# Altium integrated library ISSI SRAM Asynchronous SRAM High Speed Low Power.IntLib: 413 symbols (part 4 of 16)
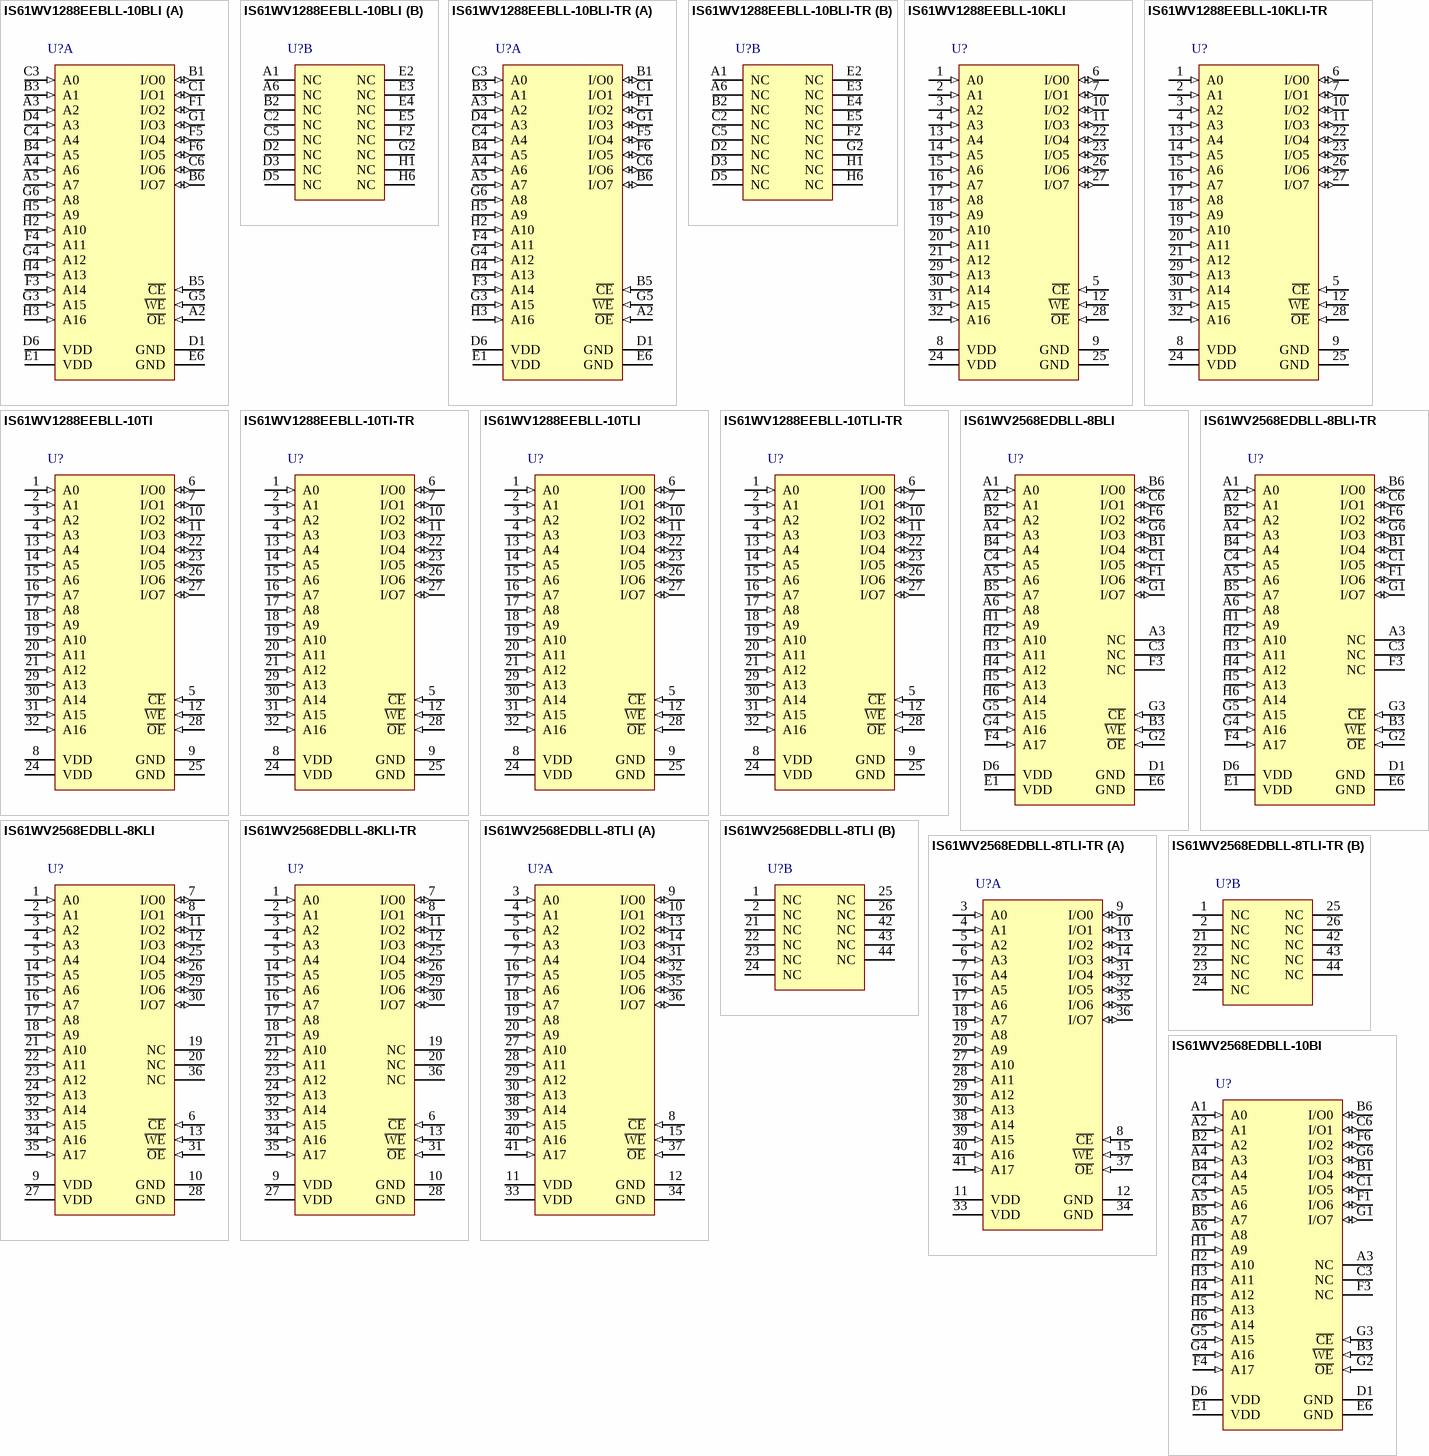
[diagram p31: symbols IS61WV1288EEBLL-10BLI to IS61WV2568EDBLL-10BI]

## IS61WV2568EDBLL-10BI
designator U?
2 M High Speed Asynchronous CMOS SRAM with ECC, 256 K x 8, -40 to 85 degC, 36-Pin BGA (TF-BGA-36); Manufacturer: Integrated Silicon Solution Inc (ISSI); PartNumber: IS61WV2568EDBLL-10BI; Density: 2M; Organization: 256K x 8; Packing: Tray / Tube; Speed (ns): 10
footprint ISSI-TF-BGA-36-6000x8000DE (BGA, 36-Balls, Body 8x6mm, Pitch 0.75mm)
pins: A1 A0 (in) "Address Input", A2 A1 (in) "Address Input", A3 NC "No Connection", A4 A3 (in) "Address Input", A5 A6 (in) "Address Input", A6 A8 (in) "Address Input", B1 I/O4 (io) "Bidirectional Port", B2 A2 (in) "Address Input", B3 ~{WE} (in) "Write Enable Input", B4 A4 (in) "Address Input", B5 A7 (in) "Address Input", B6 I/O0 (io) "Bidirectional Port", C1 I/O5 (io) "Bidirectional Port", C3 NC "No Connection", C4 A5 (in) "Address Input", C6 I/O1 (io) "Bidirectional Port", D1 GND (power) "Ground", D6 VDD (power) "Power", E1 VDD (power) "Power", E6 GND (power) "Ground", F1 I/O6 (io) "Bidirectional Port", F3 NC "No Connection", F4 A17 (in) "Address Input", F6 I/O2 (io) "Bidirectional Port", G1 I/O7 (io) "Bidirectional Port", G2 ~{OE} (in) "Output Enable Input", G3 ~{CE} (in) "Chip Enable Input", G4 A16 (in) "Address Input", G5 A15 (in) "Address Input", G6 I/O3 (io) "Bidirectional Port", H1 A9 (in) "Address Input", H2 A10 (in) "Address Input", H3 A11 (in) "Address Input", H4 A12 (in) "Address Input", H5 A13 (in) "Address Input", H6 A14 (in) "Address Input"

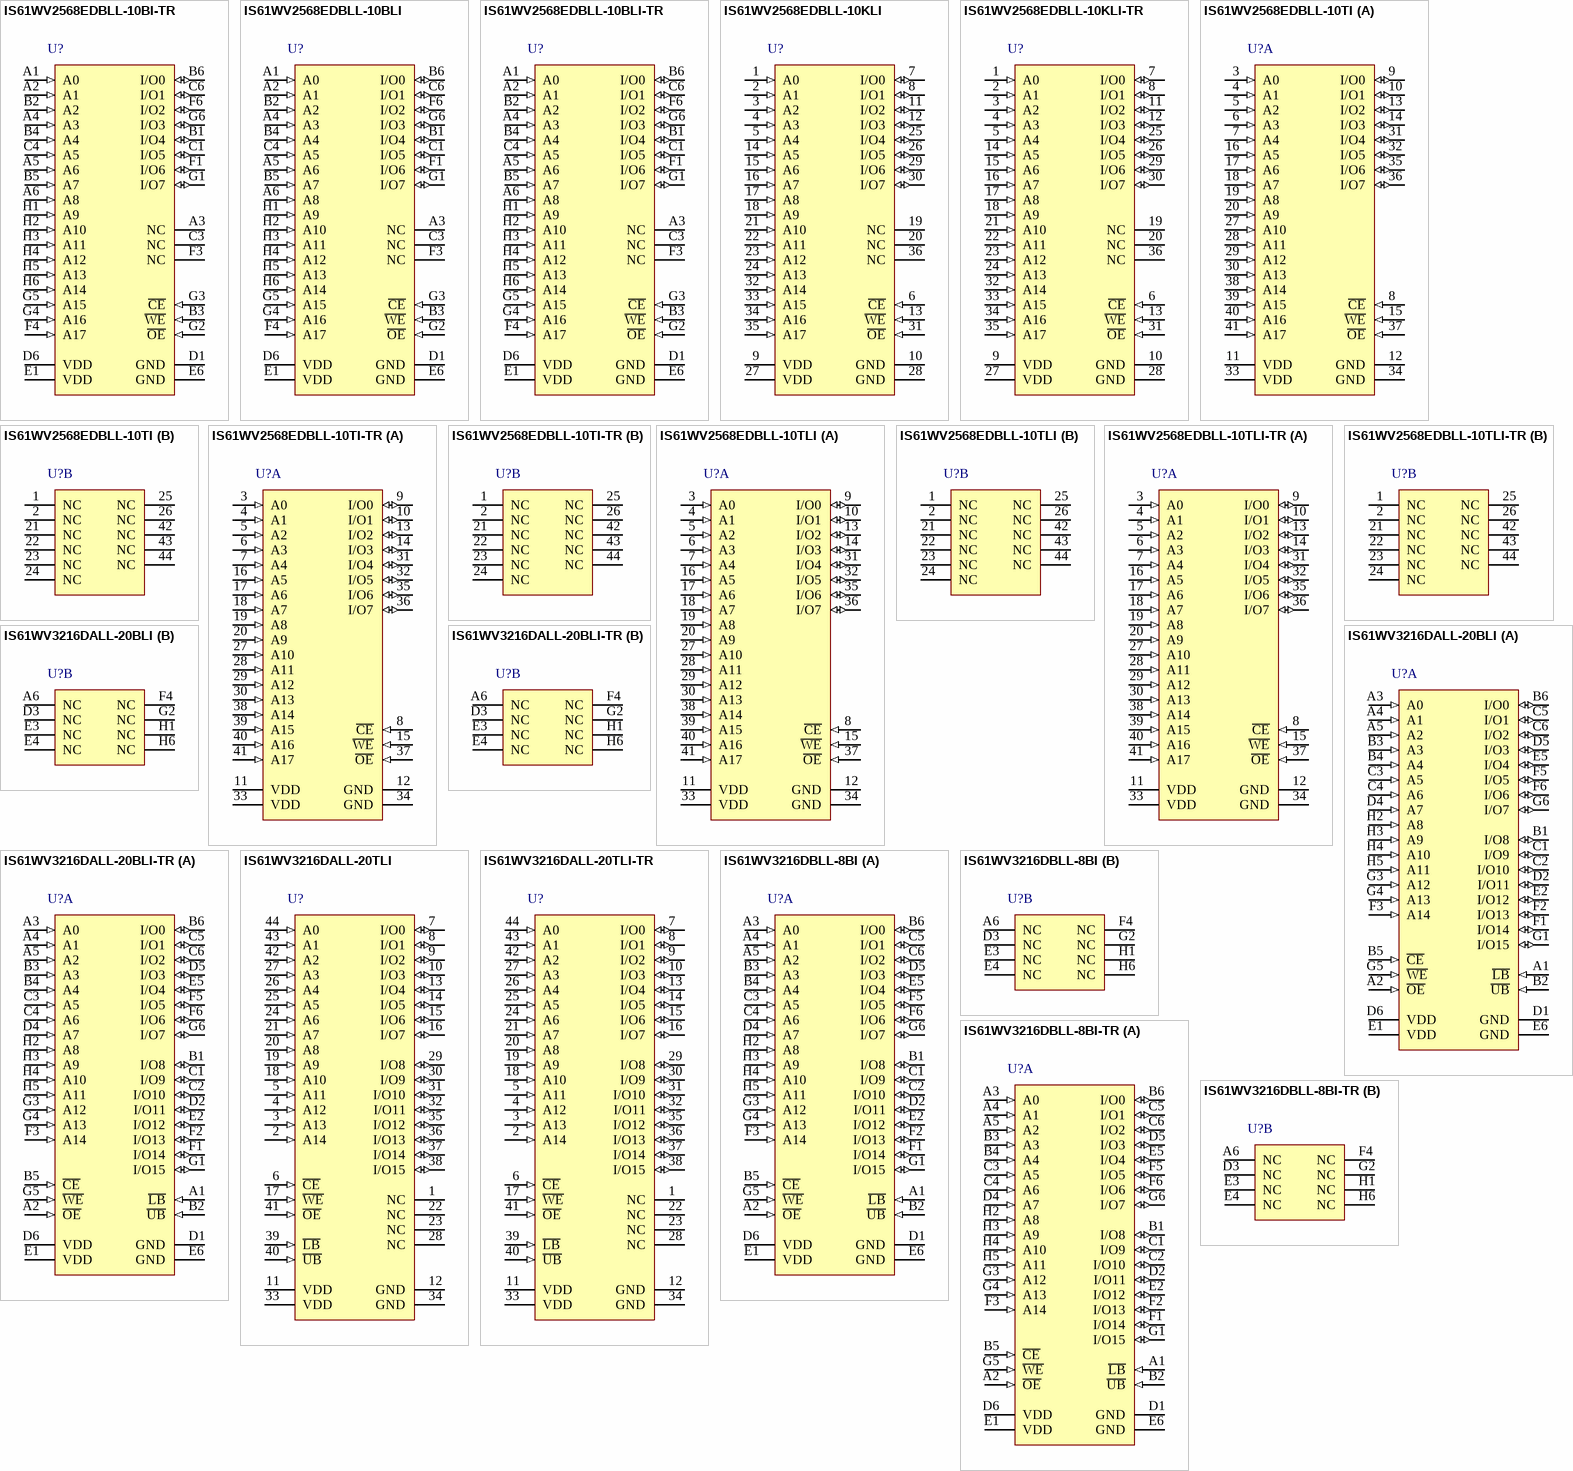
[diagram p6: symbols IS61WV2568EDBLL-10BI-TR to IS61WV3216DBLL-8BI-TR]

## IS61WV2568EDBLL-10BI-TR
designator U?
2 M High Speed Asynchronous CMOS SRAM with ECC, 256 K x 8, -40 to 85 degC, 36-Pin BGA (TF-BGA-36); Manufacturer: Integrated Silicon Solution Inc (ISSI); PartNumber: IS61WV2568EDBLL-10BI-TR; Density: 2M; Organization: 256K x 8; Packing: Tape & Reel; Speed (ns): 10
footprint ISSI-TF-BGA-36-6000x8000DE (BGA, 36-Balls, Body 8x6mm, Pitch 0.75mm)
pins: A1 A0 (in) "Address Input", A2 A1 (in) "Address Input", A3 NC "No Connection", A4 A3 (in) "Address Input", A5 A6 (in) "Address Input", A6 A8 (in) "Address Input", B1 I/O4 (io) "Bidirectional Port", B2 A2 (in) "Address Input", B3 ~{WE} (in) "Write Enable Input", B4 A4 (in) "Address Input", B5 A7 (in) "Address Input", B6 I/O0 (io) "Bidirectional Port", C1 I/O5 (io) "Bidirectional Port", C3 NC "No Connection", C4 A5 (in) "Address Input", C6 I/O1 (io) "Bidirectional Port", D1 GND (power) "Ground", D6 VDD (power) "Power", E1 VDD (power) "Power", E6 GND (power) "Ground", F1 I/O6 (io) "Bidirectional Port", F3 NC "No Connection", F4 A17 (in) "Address Input", F6 I/O2 (io) "Bidirectional Port", G1 I/O7 (io) "Bidirectional Port", G2 ~{OE} (in) "Output Enable Input", G3 ~{CE} (in) "Chip Enable Input", G4 A16 (in) "Address Input", G5 A15 (in) "Address Input", G6 I/O3 (io) "Bidirectional Port", H1 A9 (in) "Address Input", H2 A10 (in) "Address Input", H3 A11 (in) "Address Input", H4 A12 (in) "Address Input", H5 A13 (in) "Address Input", H6 A14 (in) "Address Input"

## IS61WV2568EDBLL-10BLI
designator U?
2 M High Speed Asynchronous CMOS SRAM with ECC, 256 K x 8, -40 to 85 degC, 36-Pin BGA (TF-BGA-36), Pb-Free; Manufacturer: Integrated Silicon Solution Inc (ISSI); PartNumber: IS61WV2568EDBLL-10BLI; Density: 2M; Organization: 256K x 8; Packing: Tray / Tube; Speed (ns): 10
footprint ISSI-TF-BGA-36-6000x8000DE (BGA, 36-Balls, Body 8x6mm, Pitch 0.75mm)
pins: A1 A0 (in) "Address Input", A2 A1 (in) "Address Input", A3 NC "No Connection", A4 A3 (in) "Address Input", A5 A6 (in) "Address Input", A6 A8 (in) "Address Input", B1 I/O4 (io) "Bidirectional Port", B2 A2 (in) "Address Input", B3 ~{WE} (in) "Write Enable Input", B4 A4 (in) "Address Input", B5 A7 (in) "Address Input", B6 I/O0 (io) "Bidirectional Port", C1 I/O5 (io) "Bidirectional Port", C3 NC "No Connection", C4 A5 (in) "Address Input", C6 I/O1 (io) "Bidirectional Port", D1 GND (power) "Ground", D6 VDD (power) "Power", E1 VDD (power) "Power", E6 GND (power) "Ground", F1 I/O6 (io) "Bidirectional Port", F3 NC "No Connection", F4 A17 (in) "Address Input", F6 I/O2 (io) "Bidirectional Port", G1 I/O7 (io) "Bidirectional Port", G2 ~{OE} (in) "Output Enable Input", G3 ~{CE} (in) "Chip Enable Input", G4 A16 (in) "Address Input", G5 A15 (in) "Address Input", G6 I/O3 (io) "Bidirectional Port", H1 A9 (in) "Address Input", H2 A10 (in) "Address Input", H3 A11 (in) "Address Input", H4 A12 (in) "Address Input", H5 A13 (in) "Address Input", H6 A14 (in) "Address Input"

## IS61WV2568EDBLL-10BLI-TR
designator U?
2 M High Speed Asynchronous CMOS SRAM with ECC, 256 K x 8, -40 to 85 degC, 36-Pin BGA (TF-BGA-36), Pb-Free; Manufacturer: Integrated Silicon Solution Inc (ISSI); PartNumber: IS61WV2568EDBLL-10BLI-TR; Density: 2M; Organization: 256K x 8; Packing: Tape & Reel; Speed (ns): 10
footprint ISSI-TF-BGA-36-6000x8000DE (BGA, 36-Balls, Body 8x6mm, Pitch 0.75mm)
pins: A1 A0 (in) "Address Input", A2 A1 (in) "Address Input", A3 NC "No Connection", A4 A3 (in) "Address Input", A5 A6 (in) "Address Input", A6 A8 (in) "Address Input", B1 I/O4 (io) "Bidirectional Port", B2 A2 (in) "Address Input", B3 ~{WE} (in) "Write Enable Input", B4 A4 (in) "Address Input", B5 A7 (in) "Address Input", B6 I/O0 (io) "Bidirectional Port", C1 I/O5 (io) "Bidirectional Port", C3 NC "No Connection", C4 A5 (in) "Address Input", C6 I/O1 (io) "Bidirectional Port", D1 GND (power) "Ground", D6 VDD (power) "Power", E1 VDD (power) "Power", E6 GND (power) "Ground", F1 I/O6 (io) "Bidirectional Port", F3 NC "No Connection", F4 A17 (in) "Address Input", F6 I/O2 (io) "Bidirectional Port", G1 I/O7 (io) "Bidirectional Port", G2 ~{OE} (in) "Output Enable Input", G3 ~{CE} (in) "Chip Enable Input", G4 A16 (in) "Address Input", G5 A15 (in) "Address Input", G6 I/O3 (io) "Bidirectional Port", H1 A9 (in) "Address Input", H2 A10 (in) "Address Input", H3 A11 (in) "Address Input", H4 A12 (in) "Address Input", H5 A13 (in) "Address Input", H6 A14 (in) "Address Input"

## IS61WV2568EDBLL-10KLI
designator U?
2 M High Speed Asynchronous CMOS SRAM with ECC, 256 K x 8, -40 to 85 degC, 36-Pin SOJ (SOJ-36), Pb-Free; Manufacturer: Integrated Silicon Solution Inc (ISSI); PartNumber: IS61WV2568EDBLL-10KLI; Density: 2M; Organization: 256K x 8; Packing: Tray / Tube; Speed (ns): 10
footprint ISSI-SOJ-36_N (SOJ, 36-Leads, Body 23.62x10.29mm, Pitch 1.27mm, IPC Medium Density)
pins: 1 A0 (in) "Address Input", 2 A1 (in) "Address Input", 3 A2 (in) "Address Input", 4 A3 (in) "Address Input", 5 A4 (in) "Address Input", 6 ~{CE} (in) "Chip Enable Input", 7 I/O0 (io) "Bidirectional Port", 8 I/O1 (io) "Bidirectional Port", 9 VDD (power) "Power", 10 GND (power) "Ground", 11 I/O2 (io) "Bidirectional Port", 12 I/O3 (io) "Bidirectional Port", 13 ~{WE} (in) "Write Enable Input", 14 A5 (in) "Address Input", 15 A6 (in) "Address Input", 16 A7 (in) "Address Input", 17 A8 (in) "Address Input", 18 A9 (in) "Address Input", 19 NC "No Connection", 20 NC "No Connection", 21 A10 (in) "Address Input", 22 A11 (in) "Address Input", 23 A12 (in) "Address Input", 24 A13 (in) "Address Input", 25 I/O4 (io) "Bidirectional Port", 26 I/O5 (io) "Bidirectional Port", 27 VDD (power) "Power", 28 GND (power) "Ground", 29 I/O6 (io) "Bidirectional Port", 30 I/O7 (io) "Bidirectional Port", 31 ~{OE} (in) "Output Enable Input", 32 A14 (in) "Address Input", 33 A15 (in) "Address Input", 34 A16 (in) "Address Input", 35 A17 (in) "Address Input", 36 NC "No Connection"

## IS61WV2568EDBLL-10KLI-TR
designator U?
2 M High Speed Asynchronous CMOS SRAM with ECC, 256 K x 8, -40 to 85 degC, 36-Pin SOJ (SOJ-36), Pb-Free; Manufacturer: Integrated Silicon Solution Inc (ISSI); PartNumber: IS61WV2568EDBLL-10KLI-TR; Density: 2M; Organization: 256K x 8; Packing: Tape & Reel; Speed (ns): 10
footprint ISSI-SOJ-36_N (SOJ, 36-Leads, Body 23.62x10.29mm, Pitch 1.27mm, IPC Medium Density)
pins: 1 A0 (in) "Address Input", 2 A1 (in) "Address Input", 3 A2 (in) "Address Input", 4 A3 (in) "Address Input", 5 A4 (in) "Address Input", 6 ~{CE} (in) "Chip Enable Input", 7 I/O0 (io) "Bidirectional Port", 8 I/O1 (io) "Bidirectional Port", 9 VDD (power) "Power", 10 GND (power) "Ground", 11 I/O2 (io) "Bidirectional Port", 12 I/O3 (io) "Bidirectional Port", 13 ~{WE} (in) "Write Enable Input", 14 A5 (in) "Address Input", 15 A6 (in) "Address Input", 16 A7 (in) "Address Input", 17 A8 (in) "Address Input", 18 A9 (in) "Address Input", 19 NC "No Connection", 20 NC "No Connection", 21 A10 (in) "Address Input", 22 A11 (in) "Address Input", 23 A12 (in) "Address Input", 24 A13 (in) "Address Input", 25 I/O4 (io) "Bidirectional Port", 26 I/O5 (io) "Bidirectional Port", 27 VDD (power) "Power", 28 GND (power) "Ground", 29 I/O6 (io) "Bidirectional Port", 30 I/O7 (io) "Bidirectional Port", 31 ~{OE} (in) "Output Enable Input", 32 A14 (in) "Address Input", 33 A15 (in) "Address Input", 34 A16 (in) "Address Input", 35 A17 (in) "Address Input", 36 NC "No Connection"

## IS61WV2568EDBLL-10TI
designator U?
2 M High Speed Asynchronous CMOS SRAM with ECC, 256 K x 8, -40 to 85 degC, 44-Pin SOP (TSOP-2-44); Manufacturer: Integrated Silicon Solution Inc (ISSI); PartNumber: IS61WV2568EDBLL-10TI; Density: 2M; Organization: 256K x 8; Packing: Tray / Tube; Speed (ns): 10
footprint ISSI-TSOP-2-44_N (SOP, 44-Leads, Body 18.5x10.3mm, Pitch 0.8mm, IPC Medium Density)
part A pins: 3 A0 (in) "Address Input", 4 A1 (in) "Address Input", 5 A2 (in) "Address Input", 6 A3 (in) "Address Input", 7 A4 (in) "Address Input", 8 ~{CE} (in) "Chip Enable Input", 9 I/O0 (io) "Bidirectional Port", 10 I/O1 (io) "Bidirectional Port", 11 VDD (power) "Power", 12 GND (power) "Ground", 13 I/O2 (io) "Bidirectional Port", 14 I/O3 (io) "Bidirectional Port", 15 ~{WE} (in) "Write Enable Input", 16 A5 (in) "Address Input", 17 A6 (in) "Address Input", 18 A7 (in) "Address Input", 19 A8 (in) "Address Input", 20 A9 (in) "Address Input", 27 A10 (in) "Address Input", 28 A11 (in) "Address Input", 29 A12 (in) "Address Input", 30 A13 (in) "Address Input", 31 I/O4 (io) "Bidirectional Port", 32 I/O5 (io) "Bidirectional Port", 33 VDD (power) "Power", 34 GND (power) "Ground", 35 I/O6 (io) "Bidirectional Port", 36 I/O7 (io) "Bidirectional Port", 37 ~{OE} (in) "Output Enable Input", 38 A14 (in) "Address Input", 39 A15 (in) "Address Input", 40 A16 (in) "Address Input", 41 A17 (in) "Address Input"
part B pins: 1 NC "No Connection", 2 NC "No Connection", 21 NC "No Connection", 22 NC "No Connection", 23 NC "No Connection", 24 NC "No Connection", 25 NC "No Connection", 26 NC "No Connection", 42 NC "No Connection", 43 NC "No Connection", 44 NC "No Connection"

## IS61WV2568EDBLL-10TI-TR
designator U?
2 M High Speed Asynchronous CMOS SRAM with ECC, 256 K x 8, -40 to 85 degC, 44-Pin SOP (TSOP-2-44); Manufacturer: Integrated Silicon Solution Inc (ISSI); PartNumber: IS61WV2568EDBLL-10TI-TR; Density: 2M; Organization: 256K x 8; Packing: Tape & Reel; Speed (ns): 10
footprint ISSI-TSOP-2-44_N (SOP, 44-Leads, Body 18.5x10.3mm, Pitch 0.8mm, IPC Medium Density)
part A pins: 3 A0 (in) "Address Input", 4 A1 (in) "Address Input", 5 A2 (in) "Address Input", 6 A3 (in) "Address Input", 7 A4 (in) "Address Input", 8 ~{CE} (in) "Chip Enable Input", 9 I/O0 (io) "Bidirectional Port", 10 I/O1 (io) "Bidirectional Port", 11 VDD (power) "Power", 12 GND (power) "Ground", 13 I/O2 (io) "Bidirectional Port", 14 I/O3 (io) "Bidirectional Port", 15 ~{WE} (in) "Write Enable Input", 16 A5 (in) "Address Input", 17 A6 (in) "Address Input", 18 A7 (in) "Address Input", 19 A8 (in) "Address Input", 20 A9 (in) "Address Input", 27 A10 (in) "Address Input", 28 A11 (in) "Address Input", 29 A12 (in) "Address Input", 30 A13 (in) "Address Input", 31 I/O4 (io) "Bidirectional Port", 32 I/O5 (io) "Bidirectional Port", 33 VDD (power) "Power", 34 GND (power) "Ground", 35 I/O6 (io) "Bidirectional Port", 36 I/O7 (io) "Bidirectional Port", 37 ~{OE} (in) "Output Enable Input", 38 A14 (in) "Address Input", 39 A15 (in) "Address Input", 40 A16 (in) "Address Input", 41 A17 (in) "Address Input"
part B pins: 1 NC "No Connection", 2 NC "No Connection", 21 NC "No Connection", 22 NC "No Connection", 23 NC "No Connection", 24 NC "No Connection", 25 NC "No Connection", 26 NC "No Connection", 42 NC "No Connection", 43 NC "No Connection", 44 NC "No Connection"

## IS61WV2568EDBLL-10TLI
designator U?
2 M High Speed Asynchronous CMOS SRAM with ECC, 256 K x 8, -40 to 85 degC, 44-Pin SOP (TSOP-2-44), Pb-Free; Manufacturer: Integrated Silicon Solution Inc (ISSI); PartNumber: IS61WV2568EDBLL-10TLI; Density: 2M; Organization: 256K x 8; Packing: Tray / Tube; Speed (ns): 10
footprint ISSI-TSOP-2-44_N (SOP, 44-Leads, Body 18.5x10.3mm, Pitch 0.8mm, IPC Medium Density)
part A pins: 3 A0 (in) "Address Input", 4 A1 (in) "Address Input", 5 A2 (in) "Address Input", 6 A3 (in) "Address Input", 7 A4 (in) "Address Input", 8 ~{CE} (in) "Chip Enable Input", 9 I/O0 (io) "Bidirectional Port", 10 I/O1 (io) "Bidirectional Port", 11 VDD (power) "Power", 12 GND (power) "Ground", 13 I/O2 (io) "Bidirectional Port", 14 I/O3 (io) "Bidirectional Port", 15 ~{WE} (in) "Write Enable Input", 16 A5 (in) "Address Input", 17 A6 (in) "Address Input", 18 A7 (in) "Address Input", 19 A8 (in) "Address Input", 20 A9 (in) "Address Input", 27 A10 (in) "Address Input", 28 A11 (in) "Address Input", 29 A12 (in) "Address Input", 30 A13 (in) "Address Input", 31 I/O4 (io) "Bidirectional Port", 32 I/O5 (io) "Bidirectional Port", 33 VDD (power) "Power", 34 GND (power) "Ground", 35 I/O6 (io) "Bidirectional Port", 36 I/O7 (io) "Bidirectional Port", 37 ~{OE} (in) "Output Enable Input", 38 A14 (in) "Address Input", 39 A15 (in) "Address Input", 40 A16 (in) "Address Input", 41 A17 (in) "Address Input"
part B pins: 1 NC "No Connection", 2 NC "No Connection", 21 NC "No Connection", 22 NC "No Connection", 23 NC "No Connection", 24 NC "No Connection", 25 NC "No Connection", 26 NC "No Connection", 42 NC "No Connection", 43 NC "No Connection", 44 NC "No Connection"

## IS61WV2568EDBLL-10TLI-TR
designator U?
2 M High Speed Asynchronous CMOS SRAM with ECC, 256 K x 8, -40 to 85 degC, 44-Pin SOP (TSOP-2-44), Pb-Free; Manufacturer: Integrated Silicon Solution Inc (ISSI); PartNumber: IS61WV2568EDBLL-10TLI-TR; Density: 2M; Organization: 256K x 8; Packing: Tape & Reel; Speed (ns): 10
footprint ISSI-TSOP-2-44_N (SOP, 44-Leads, Body 18.5x10.3mm, Pitch 0.8mm, IPC Medium Density)
part A pins: 3 A0 (in) "Address Input", 4 A1 (in) "Address Input", 5 A2 (in) "Address Input", 6 A3 (in) "Address Input", 7 A4 (in) "Address Input", 8 ~{CE} (in) "Chip Enable Input", 9 I/O0 (io) "Bidirectional Port", 10 I/O1 (io) "Bidirectional Port", 11 VDD (power) "Power", 12 GND (power) "Ground", 13 I/O2 (io) "Bidirectional Port", 14 I/O3 (io) "Bidirectional Port", 15 ~{WE} (in) "Write Enable Input", 16 A5 (in) "Address Input", 17 A6 (in) "Address Input", 18 A7 (in) "Address Input", 19 A8 (in) "Address Input", 20 A9 (in) "Address Input", 27 A10 (in) "Address Input", 28 A11 (in) "Address Input", 29 A12 (in) "Address Input", 30 A13 (in) "Address Input", 31 I/O4 (io) "Bidirectional Port", 32 I/O5 (io) "Bidirectional Port", 33 VDD (power) "Power", 34 GND (power) "Ground", 35 I/O6 (io) "Bidirectional Port", 36 I/O7 (io) "Bidirectional Port", 37 ~{OE} (in) "Output Enable Input", 38 A14 (in) "Address Input", 39 A15 (in) "Address Input", 40 A16 (in) "Address Input", 41 A17 (in) "Address Input"
part B pins: 1 NC "No Connection", 2 NC "No Connection", 21 NC "No Connection", 22 NC "No Connection", 23 NC "No Connection", 24 NC "No Connection", 25 NC "No Connection", 26 NC "No Connection", 42 NC "No Connection", 43 NC "No Connection", 44 NC "No Connection"

## IS61WV3216DALL-20BLI
designator U?
512 K High Speed Asynchronous CMOS SRAM, 32 K x 16, -40 to 85 degC, 48-Pin BGA (TF-BGA-48), Pb-Free; Manufacturer: Integrated Silicon Solution Inc (ISSI); PartNumber: IS61WV3216DALL-20BLI; Density: 512K; Organization: 32K x 16; Packing: Tray / Tube; Speed (ns): 20
footprint ISSI-TF-BGA-48-6000X8000DE (BGA, 48-Balls, Body 8x6mm, Pitch 0.75mm)
part A pins: A1 ~{LB} (in) "Lower-byte Control(I/O0-I/O7)", A2 ~{OE} (in) "Output Enable Input", A3 A0 (in) "Address Input", A4 A1 (in) "Address Input", A5 A2 (in) "Address Input", B1 I/O8 (io) "Data Input/Output", B2 ~{UB} (in) "Upper-byte Control(I/O8-I/O15)", B3 A3 (in) "Address Input", B4 A4 (in) "Address Input", B5 ~{CE} (in) "Chip Enable Input", B6 I/O0 (io) "Data Input/Output", C1 I/O9 (io) "Data Input/Output", C2 I/O10 (io) "Data Input/Output", C3 A5 (in) "Address Input", C4 A6 (in) "Address Input", C5 I/O1 (io) "Data Input/Output", C6 I/O2 (io) "Data Input/Output", D1 GND (power) "Ground", D2 I/O11 (io) "Data Input/Output", D4 A7 (in) "Address Input", D5 I/O3 (io) "Data Input/Output", D6 VDD (power) "Power", E1 VDD (power) "Power", E2 I/O12 (io) "Data Input/Output", E5 I/O4 (io) "Data Input/Output", E6 GND (power) "Ground", F1 I/O14 (io) "Data Input/Output", F2 I/O13 (io) "Data Input/Output", F3 A14 (in) "Address Input", F5 I/O5 (io) "Data Input/Output", F6 I/O6 (io) "Data Input/Output", G1 I/O15 (io) "Data Input/Output", G3 A12 (in) "Address Input", G4 A13 (in) "Address Input", G5 ~{WE} (in) "Write Enable Input", G6 I/O7 (io) "Data Input/Output", H2 A8 (in) "Address Input", H3 A9 (in) "Address Input", H4 A10 (in) "Address Input", H5 A11 (in) "Address Input"
part B pins: A6 NC "No Connection", D3 NC "No Connection", E3 NC "No Connection", E4 NC "No Connection", F4 NC "No Connection", G2 NC "No Connection", H1 NC "No Connection", H6 NC "No Connection"

## IS61WV3216DALL-20BLI-TR
designator U?
512 K High Speed Asynchronous CMOS SRAM, 32 K x 16, -40 to 85 degC, 48-Pin BGA (TF-BGA-48), Pb-Free; Manufacturer: Integrated Silicon Solution Inc (ISSI); PartNumber: IS61WV3216DALL-20BLI-TR; Density: 512K; Organization: 32K x 16; Packing: Tape & Reel; Speed (ns): 20
footprint ISSI-TF-BGA-48-6000X8000DE (BGA, 48-Balls, Body 8x6mm, Pitch 0.75mm)
part A pins: A1 ~{LB} (in) "Lower-byte Control(I/O0-I/O7)", A2 ~{OE} (in) "Output Enable Input", A3 A0 (in) "Address Input", A4 A1 (in) "Address Input", A5 A2 (in) "Address Input", B1 I/O8 (io) "Data Input/Output", B2 ~{UB} (in) "Upper-byte Control(I/O8-I/O15)", B3 A3 (in) "Address Input", B4 A4 (in) "Address Input", B5 ~{CE} (in) "Chip Enable Input", B6 I/O0 (io) "Data Input/Output", C1 I/O9 (io) "Data Input/Output", C2 I/O10 (io) "Data Input/Output", C3 A5 (in) "Address Input", C4 A6 (in) "Address Input", C5 I/O1 (io) "Data Input/Output", C6 I/O2 (io) "Data Input/Output", D1 GND (power) "Ground", D2 I/O11 (io) "Data Input/Output", D4 A7 (in) "Address Input", D5 I/O3 (io) "Data Input/Output", D6 VDD (power) "Power", E1 VDD (power) "Power", E2 I/O12 (io) "Data Input/Output", E5 I/O4 (io) "Data Input/Output", E6 GND (power) "Ground", F1 I/O14 (io) "Data Input/Output", F2 I/O13 (io) "Data Input/Output", F3 A14 (in) "Address Input", F5 I/O5 (io) "Data Input/Output", F6 I/O6 (io) "Data Input/Output", G1 I/O15 (io) "Data Input/Output", G3 A12 (in) "Address Input", G4 A13 (in) "Address Input", G5 ~{WE} (in) "Write Enable Input", G6 I/O7 (io) "Data Input/Output", H2 A8 (in) "Address Input", H3 A9 (in) "Address Input", H4 A10 (in) "Address Input", H5 A11 (in) "Address Input"
part B pins: A6 NC "No Connection", D3 NC "No Connection", E3 NC "No Connection", E4 NC "No Connection", F4 NC "No Connection", G2 NC "No Connection", H1 NC "No Connection", H6 NC "No Connection"

## IS61WV3216DALL-20TLI
designator U?
512 K High Speed Asynchronous CMOS SRAM, 32 K x 16, -40 to 85 degC, 44-Pin SOP (TSOP-2-44), Pb-Free; Manufacturer: Integrated Silicon Solution Inc (ISSI); PartNumber: IS61WV3216DALL-20TLI; Density: 512K; Organization: 32K x 16; Packing: Tray / Tube; Speed (ns): 20
footprint ISSI-TSOP-2-44_N (SOP, 44-Leads, Body 18.5x10.3mm, Pitch 0.8mm, IPC Medium Density)
pins: 1 NC "No Connection", 2 A14 (in) "Address Input", 3 A13 (in) "Address Input", 4 A12 (in) "Address Input", 5 A11 (in) "Address Input", 6 ~{CE} (in) "Chip Enable Input", 7 I/O0 (io) "Data Input/Output", 8 I/O1 (io) "Data Input/Output", 9 I/O2 (io) "Data Input/Output", 10 I/O3 (io) "Data Input/Output", 11 VDD (power) "Power", 12 GND (power) "Ground", 13 I/O4 (io) "Data Input/Output", 14 I/O5 (io) "Data Input/Output", 15 I/O6 (io) "Data Input/Output", 16 I/O7 (io) "Data Input/Output", 17 ~{WE} (in) "Write Enable Input", 18 A10 (in) "Address Input", 19 A9 (in) "Address Input", 20 A8 (in) "Address Input", 21 A7 (in) "Address Input", 22 NC "No Connection", 23 NC "No Connection", 24 A6 (in) "Address Input", 25 A5 (in) "Address Input", 26 A4 (in) "Address Input", 27 A3 (in) "Address Input", 28 NC "No Connection", 29 I/O8 (io) "Data Input/Output", 30 I/O9 (io) "Data Input/Output", 31 I/O10 (io) "Data Input/Output", 32 I/O11 (io) "Data Input/Output", 33 VDD (power) "Power", 34 GND (power) "Ground", 35 I/O12 (io) "Data Input/Output", 36 I/O13 (io) "Data Input/Output", 37 I/O14 (io) "Data Input/Output", 38 I/O15 (io) "Data Input/Output", 39 ~{LB} (in) "Lower-byte Control (I/O0-I/O7)", 40 ~{UB} (in) "Upper-byte Control (I/O8-I/O15)", 41 ~{OE} (in) "Output Enable Input", 42 A2 (in) "Address Input", 43 A1 (in) "Address Input", 44 A0 (in) "Address Input"

## IS61WV3216DALL-20TLI-TR
designator U?
512 K High Speed Asynchronous CMOS SRAM, 32 K x 16, -40 to 85 degC, 44-Pin SOP (TSOP-2-44), Pb-Free; Manufacturer: Integrated Silicon Solution Inc (ISSI); PartNumber: IS61WV3216DALL-20TLI-TR; Density: 512K; Organization: 32K x 16; Packing: Tape & Reel; Speed (ns): 20
footprint ISSI-TSOP-2-44_N (SOP, 44-Leads, Body 18.5x10.3mm, Pitch 0.8mm, IPC Medium Density)
pins: 1 NC "No Connection", 2 A14 (in) "Address Input", 3 A13 (in) "Address Input", 4 A12 (in) "Address Input", 5 A11 (in) "Address Input", 6 ~{CE} (in) "Chip Enable Input", 7 I/O0 (io) "Data Input/Output", 8 I/O1 (io) "Data Input/Output", 9 I/O2 (io) "Data Input/Output", 10 I/O3 (io) "Data Input/Output", 11 VDD (power) "Power", 12 GND (power) "Ground", 13 I/O4 (io) "Data Input/Output", 14 I/O5 (io) "Data Input/Output", 15 I/O6 (io) "Data Input/Output", 16 I/O7 (io) "Data Input/Output", 17 ~{WE} (in) "Write Enable Input", 18 A10 (in) "Address Input", 19 A9 (in) "Address Input", 20 A8 (in) "Address Input", 21 A7 (in) "Address Input", 22 NC "No Connection", 23 NC "No Connection", 24 A6 (in) "Address Input", 25 A5 (in) "Address Input", 26 A4 (in) "Address Input", 27 A3 (in) "Address Input", 28 NC "No Connection", 29 I/O8 (io) "Data Input/Output", 30 I/O9 (io) "Data Input/Output", 31 I/O10 (io) "Data Input/Output", 32 I/O11 (io) "Data Input/Output", 33 VDD (power) "Power", 34 GND (power) "Ground", 35 I/O12 (io) "Data Input/Output", 36 I/O13 (io) "Data Input/Output", 37 I/O14 (io) "Data Input/Output", 38 I/O15 (io) "Data Input/Output", 39 ~{LB} (in) "Lower-byte Control (I/O0-I/O7)", 40 ~{UB} (in) "Upper-byte Control (I/O8-I/O15)", 41 ~{OE} (in) "Output Enable Input", 42 A2 (in) "Address Input", 43 A1 (in) "Address Input", 44 A0 (in) "Address Input"

## IS61WV3216DBLL-8BI
designator U?
512 K High Speed Asynchronous CMOS SRAM, 32 K x 16, -40 to 85 degC, 48-Pin BGA (TF-BGA-48); Manufacturer: Integrated Silicon Solution Inc (ISSI); PartNumber: IS61WV3216DBLL-8BI; Density: 512K; Organization: 32K x 16; Packing: Tray / Tube; Speed (ns): 8
footprint ISSI-TF-BGA-48-6000X8000DE (BGA, 48-Balls, Body 8x6mm, Pitch 0.75mm)
part A pins: A1 ~{LB} (in) "Lower-byte Control(I/O0-I/O7)", A2 ~{OE} (in) "Output Enable Input", A3 A0 (in) "Address Input", A4 A1 (in) "Address Input", A5 A2 (in) "Address Input", B1 I/O8 (io) "Data Input/Output", B2 ~{UB} (in) "Upper-byte Control(I/O8-I/O15)", B3 A3 (in) "Address Input", B4 A4 (in) "Address Input", B5 ~{CE} (in) "Chip Enable Input", B6 I/O0 (io) "Data Input/Output", C1 I/O9 (io) "Data Input/Output", C2 I/O10 (io) "Data Input/Output", C3 A5 (in) "Address Input", C4 A6 (in) "Address Input", C5 I/O1 (io) "Data Input/Output", C6 I/O2 (io) "Data Input/Output", D1 GND (power) "Ground", D2 I/O11 (io) "Data Input/Output", D4 A7 (in) "Address Input", D5 I/O3 (io) "Data Input/Output", D6 VDD (power) "Power", E1 VDD (power) "Power", E2 I/O12 (io) "Data Input/Output", E5 I/O4 (io) "Data Input/Output", E6 GND (power) "Ground", F1 I/O14 (io) "Data Input/Output", F2 I/O13 (io) "Data Input/Output", F3 A14 (in) "Address Input", F5 I/O5 (io) "Data Input/Output", F6 I/O6 (io) "Data Input/Output", G1 I/O15 (io) "Data Input/Output", G3 A12 (in) "Address Input", G4 A13 (in) "Address Input", G5 ~{WE} (in) "Write Enable Input", G6 I/O7 (io) "Data Input/Output", H2 A8 (in) "Address Input", H3 A9 (in) "Address Input", H4 A10 (in) "Address Input", H5 A11 (in) "Address Input"
part B pins: A6 NC "No Connection", D3 NC "No Connection", E3 NC "No Connection", E4 NC "No Connection", F4 NC "No Connection", G2 NC "No Connection", H1 NC "No Connection", H6 NC "No Connection"

## IS61WV3216DBLL-8BI-TR
designator U?
512 K High Speed Asynchronous CMOS SRAM, 32 K x 16, -40 to 85 degC, 48-Pin BGA (TF-BGA-48); Manufacturer: Integrated Silicon Solution Inc (ISSI); PartNumber: IS61WV3216DBLL-8BI-TR; Density: 512K; Organization: 32K x 16; Packing: Tape & Reel; Speed (ns): 8
footprint ISSI-TF-BGA-48-6000X8000DE (BGA, 48-Balls, Body 8x6mm, Pitch 0.75mm)
part A pins: A1 ~{LB} (in) "Lower-byte Control(I/O0-I/O7)", A2 ~{OE} (in) "Output Enable Input", A3 A0 (in) "Address Input", A4 A1 (in) "Address Input", A5 A2 (in) "Address Input", B1 I/O8 (io) "Data Input/Output", B2 ~{UB} (in) "Upper-byte Control(I/O8-I/O15)", B3 A3 (in) "Address Input", B4 A4 (in) "Address Input", B5 ~{CE} (in) "Chip Enable Input", B6 I/O0 (io) "Data Input/Output", C1 I/O9 (io) "Data Input/Output", C2 I/O10 (io) "Data Input/Output", C3 A5 (in) "Address Input", C4 A6 (in) "Address Input", C5 I/O1 (io) "Data Input/Output", C6 I/O2 (io) "Data Input/Output", D1 GND (power) "Ground", D2 I/O11 (io) "Data Input/Output", D4 A7 (in) "Address Input", D5 I/O3 (io) "Data Input/Output", D6 VDD (power) "Power", E1 VDD (power) "Power", E2 I/O12 (io) "Data Input/Output", E5 I/O4 (io) "Data Input/Output", E6 GND (power) "Ground", F1 I/O14 (io) "Data Input/Output", F2 I/O13 (io) "Data Input/Output", F3 A14 (in) "Address Input", F5 I/O5 (io) "Data Input/Output", F6 I/O6 (io) "Data Input/Output", G1 I/O15 (io) "Data Input/Output", G3 A12 (in) "Address Input", G4 A13 (in) "Address Input", G5 ~{WE} (in) "Write Enable Input", G6 I/O7 (io) "Data Input/Output", H2 A8 (in) "Address Input", H3 A9 (in) "Address Input", H4 A10 (in) "Address Input", H5 A11 (in) "Address Input"
part B pins: A6 NC "No Connection", D3 NC "No Connection", E3 NC "No Connection", E4 NC "No Connection", F4 NC "No Connection", G2 NC "No Connection", H1 NC "No Connection", H6 NC "No Connection"

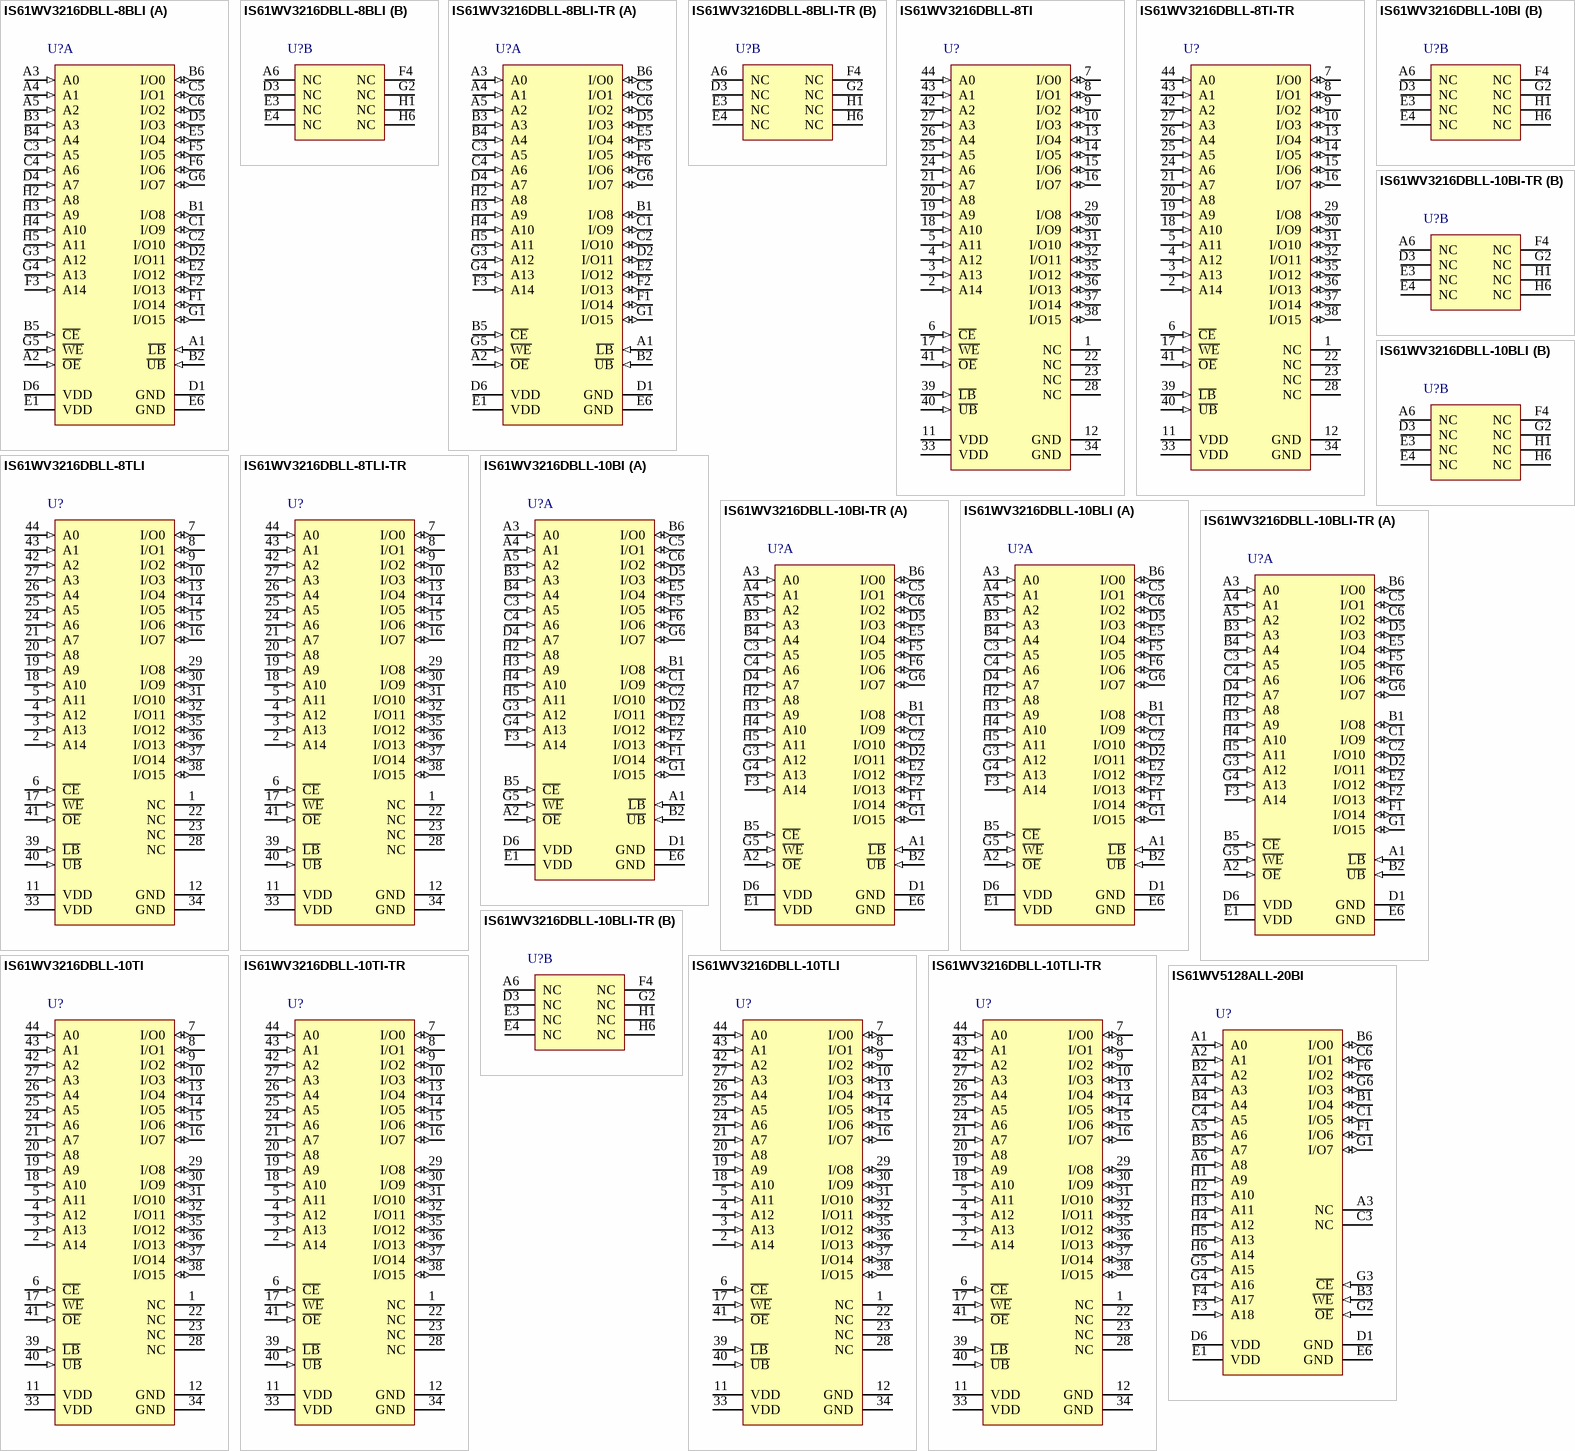
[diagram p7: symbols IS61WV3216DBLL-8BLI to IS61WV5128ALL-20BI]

## IS61WV3216DBLL-8BLI
designator U?
512 K High Speed Asynchronous CMOS SRAM, 32 K x 16, -40 to 85 degC, 48-Pin BGA (TF-BGA-48), Pb-Free; Manufacturer: Integrated Silicon Solution Inc (ISSI); PartNumber: IS61WV3216DBLL-8BLI; Density: 512K; Organization: 32K x 16; Packing: Tray / Tube; Speed (ns): 8
footprint ISSI-TF-BGA-48-6000X8000DE (BGA, 48-Balls, Body 8x6mm, Pitch 0.75mm)
part A pins: A1 ~{LB} (in) "Lower-byte Control(I/O0-I/O7)", A2 ~{OE} (in) "Output Enable Input", A3 A0 (in) "Address Input", A4 A1 (in) "Address Input", A5 A2 (in) "Address Input", B1 I/O8 (io) "Data Input/Output", B2 ~{UB} (in) "Upper-byte Control(I/O8-I/O15)", B3 A3 (in) "Address Input", B4 A4 (in) "Address Input", B5 ~{CE} (in) "Chip Enable Input", B6 I/O0 (io) "Data Input/Output", C1 I/O9 (io) "Data Input/Output", C2 I/O10 (io) "Data Input/Output", C3 A5 (in) "Address Input", C4 A6 (in) "Address Input", C5 I/O1 (io) "Data Input/Output", C6 I/O2 (io) "Data Input/Output", D1 GND (power) "Ground", D2 I/O11 (io) "Data Input/Output", D4 A7 (in) "Address Input", D5 I/O3 (io) "Data Input/Output", D6 VDD (power) "Power", E1 VDD (power) "Power", E2 I/O12 (io) "Data Input/Output", E5 I/O4 (io) "Data Input/Output", E6 GND (power) "Ground", F1 I/O14 (io) "Data Input/Output", F2 I/O13 (io) "Data Input/Output", F3 A14 (in) "Address Input", F5 I/O5 (io) "Data Input/Output", F6 I/O6 (io) "Data Input/Output", G1 I/O15 (io) "Data Input/Output", G3 A12 (in) "Address Input", G4 A13 (in) "Address Input", G5 ~{WE} (in) "Write Enable Input", G6 I/O7 (io) "Data Input/Output", H2 A8 (in) "Address Input", H3 A9 (in) "Address Input", H4 A10 (in) "Address Input", H5 A11 (in) "Address Input"
part B pins: A6 NC "No Connection", D3 NC "No Connection", E3 NC "No Connection", E4 NC "No Connection", F4 NC "No Connection", G2 NC "No Connection", H1 NC "No Connection", H6 NC "No Connection"

## IS61WV3216DBLL-8BLI-TR
designator U?
512 K High Speed Asynchronous CMOS SRAM, 32 K x 16, -40 to 85 degC, 48-Pin BGA (TF-BGA-48), Pb-Free; Manufacturer: Integrated Silicon Solution Inc (ISSI); PartNumber: IS61WV3216DBLL-8BLI-TR; Density: 512K; Organization: 32K x 16; Packing: Tape & Reel; Speed (ns): 8
footprint ISSI-TF-BGA-48-6000X8000DE (BGA, 48-Balls, Body 8x6mm, Pitch 0.75mm)
part A pins: A1 ~{LB} (in) "Lower-byte Control(I/O0-I/O7)", A2 ~{OE} (in) "Output Enable Input", A3 A0 (in) "Address Input", A4 A1 (in) "Address Input", A5 A2 (in) "Address Input", B1 I/O8 (io) "Data Input/Output", B2 ~{UB} (in) "Upper-byte Control(I/O8-I/O15)", B3 A3 (in) "Address Input", B4 A4 (in) "Address Input", B5 ~{CE} (in) "Chip Enable Input", B6 I/O0 (io) "Data Input/Output", C1 I/O9 (io) "Data Input/Output", C2 I/O10 (io) "Data Input/Output", C3 A5 (in) "Address Input", C4 A6 (in) "Address Input", C5 I/O1 (io) "Data Input/Output", C6 I/O2 (io) "Data Input/Output", D1 GND (power) "Ground", D2 I/O11 (io) "Data Input/Output", D4 A7 (in) "Address Input", D5 I/O3 (io) "Data Input/Output", D6 VDD (power) "Power", E1 VDD (power) "Power", E2 I/O12 (io) "Data Input/Output", E5 I/O4 (io) "Data Input/Output", E6 GND (power) "Ground", F1 I/O14 (io) "Data Input/Output", F2 I/O13 (io) "Data Input/Output", F3 A14 (in) "Address Input", F5 I/O5 (io) "Data Input/Output", F6 I/O6 (io) "Data Input/Output", G1 I/O15 (io) "Data Input/Output", G3 A12 (in) "Address Input", G4 A13 (in) "Address Input", G5 ~{WE} (in) "Write Enable Input", G6 I/O7 (io) "Data Input/Output", H2 A8 (in) "Address Input", H3 A9 (in) "Address Input", H4 A10 (in) "Address Input", H5 A11 (in) "Address Input"
part B pins: A6 NC "No Connection", D3 NC "No Connection", E3 NC "No Connection", E4 NC "No Connection", F4 NC "No Connection", G2 NC "No Connection", H1 NC "No Connection", H6 NC "No Connection"

## IS61WV3216DBLL-8TI
designator U?
512 K High Speed Asynchronous CMOS SRAM, 32 K x 16, -40 to 85 degC, 44-Pin SOP (TSOP-2-44); Manufacturer: Integrated Silicon Solution Inc (ISSI); PartNumber: IS61WV3216DBLL-8TI; Density: 512K; Organization: 32K x 16; Packing: Tray / Tube; Speed (ns): 8
footprint ISSI-TSOP-2-44_N (SOP, 44-Leads, Body 18.5x10.3mm, Pitch 0.8mm, IPC Medium Density)
pins: 1 NC "No Connection", 2 A14 (in) "Address Input", 3 A13 (in) "Address Input", 4 A12 (in) "Address Input", 5 A11 (in) "Address Input", 6 ~{CE} (in) "Chip Enable Input", 7 I/O0 (io) "Data Input/Output", 8 I/O1 (io) "Data Input/Output", 9 I/O2 (io) "Data Input/Output", 10 I/O3 (io) "Data Input/Output", 11 VDD (power) "Power", 12 GND (power) "Ground", 13 I/O4 (io) "Data Input/Output", 14 I/O5 (io) "Data Input/Output", 15 I/O6 (io) "Data Input/Output", 16 I/O7 (io) "Data Input/Output", 17 ~{WE} (in) "Write Enable Input", 18 A10 (in) "Address Input", 19 A9 (in) "Address Input", 20 A8 (in) "Address Input", 21 A7 (in) "Address Input", 22 NC "No Connection", 23 NC "No Connection", 24 A6 (in) "Address Input", 25 A5 (in) "Address Input", 26 A4 (in) "Address Input", 27 A3 (in) "Address Input", 28 NC "No Connection", 29 I/O8 (io) "Data Input/Output", 30 I/O9 (io) "Data Input/Output", 31 I/O10 (io) "Data Input/Output", 32 I/O11 (io) "Data Input/Output", 33 VDD (power) "Power", 34 GND (power) "Ground", 35 I/O12 (io) "Data Input/Output", 36 I/O13 (io) "Data Input/Output", 37 I/O14 (io) "Data Input/Output", 38 I/O15 (io) "Data Input/Output", 39 ~{LB} (in) "Lower-byte Control (I/O0-I/O7)", 40 ~{UB} (in) "Upper-byte Control (I/O8-I/O15)", 41 ~{OE} (in) "Output Enable Input", 42 A2 (in) "Address Input", 43 A1 (in) "Address Input", 44 A0 (in) "Address Input"

## IS61WV3216DBLL-8TI-TR
designator U?
512 K High Speed Asynchronous CMOS SRAM, 32 K x 16, -40 to 85 degC, 44-Pin SOP (TSOP-2-44); Manufacturer: Integrated Silicon Solution Inc (ISSI); PartNumber: IS61WV3216DBLL-8TI-TR; Density: 512K; Organization: 32K x 16; Packing: Tape & Reel; Speed (ns): 8
footprint ISSI-TSOP-2-44_N (SOP, 44-Leads, Body 18.5x10.3mm, Pitch 0.8mm, IPC Medium Density)
pins: 1 NC "No Connection", 2 A14 (in) "Address Input", 3 A13 (in) "Address Input", 4 A12 (in) "Address Input", 5 A11 (in) "Address Input", 6 ~{CE} (in) "Chip Enable Input", 7 I/O0 (io) "Data Input/Output", 8 I/O1 (io) "Data Input/Output", 9 I/O2 (io) "Data Input/Output", 10 I/O3 (io) "Data Input/Output", 11 VDD (power) "Power", 12 GND (power) "Ground", 13 I/O4 (io) "Data Input/Output", 14 I/O5 (io) "Data Input/Output", 15 I/O6 (io) "Data Input/Output", 16 I/O7 (io) "Data Input/Output", 17 ~{WE} (in) "Write Enable Input", 18 A10 (in) "Address Input", 19 A9 (in) "Address Input", 20 A8 (in) "Address Input", 21 A7 (in) "Address Input", 22 NC "No Connection", 23 NC "No Connection", 24 A6 (in) "Address Input", 25 A5 (in) "Address Input", 26 A4 (in) "Address Input", 27 A3 (in) "Address Input", 28 NC "No Connection", 29 I/O8 (io) "Data Input/Output", 30 I/O9 (io) "Data Input/Output", 31 I/O10 (io) "Data Input/Output", 32 I/O11 (io) "Data Input/Output", 33 VDD (power) "Power", 34 GND (power) "Ground", 35 I/O12 (io) "Data Input/Output", 36 I/O13 (io) "Data Input/Output", 37 I/O14 (io) "Data Input/Output", 38 I/O15 (io) "Data Input/Output", 39 ~{LB} (in) "Lower-byte Control (I/O0-I/O7)", 40 ~{UB} (in) "Upper-byte Control (I/O8-I/O15)", 41 ~{OE} (in) "Output Enable Input", 42 A2 (in) "Address Input", 43 A1 (in) "Address Input", 44 A0 (in) "Address Input"

## IS61WV3216DBLL-8TLI
designator U?
512 K High Speed Asynchronous CMOS SRAM, 32 K x 16, -40 to 85 degC, 44-Pin SOP (TSOP-2-44), Pb-Free; Manufacturer: Integrated Silicon Solution Inc (ISSI); PartNumber: IS61WV3216DBLL-8TLI; Density: 512K; Organization: 32K x 16; Packing: Tray / Tube; Speed (ns): 8
footprint ISSI-TSOP-2-44_N (SOP, 44-Leads, Body 18.5x10.3mm, Pitch 0.8mm, IPC Medium Density)
pins: 1 NC "No Connection", 2 A14 (in) "Address Input", 3 A13 (in) "Address Input", 4 A12 (in) "Address Input", 5 A11 (in) "Address Input", 6 ~{CE} (in) "Chip Enable Input", 7 I/O0 (io) "Data Input/Output", 8 I/O1 (io) "Data Input/Output", 9 I/O2 (io) "Data Input/Output", 10 I/O3 (io) "Data Input/Output", 11 VDD (power) "Power", 12 GND (power) "Ground", 13 I/O4 (io) "Data Input/Output", 14 I/O5 (io) "Data Input/Output", 15 I/O6 (io) "Data Input/Output", 16 I/O7 (io) "Data Input/Output", 17 ~{WE} (in) "Write Enable Input", 18 A10 (in) "Address Input", 19 A9 (in) "Address Input", 20 A8 (in) "Address Input", 21 A7 (in) "Address Input", 22 NC "No Connection", 23 NC "No Connection", 24 A6 (in) "Address Input", 25 A5 (in) "Address Input", 26 A4 (in) "Address Input", 27 A3 (in) "Address Input", 28 NC "No Connection", 29 I/O8 (io) "Data Input/Output", 30 I/O9 (io) "Data Input/Output", 31 I/O10 (io) "Data Input/Output", 32 I/O11 (io) "Data Input/Output", 33 VDD (power) "Power", 34 GND (power) "Ground", 35 I/O12 (io) "Data Input/Output", 36 I/O13 (io) "Data Input/Output", 37 I/O14 (io) "Data Input/Output", 38 I/O15 (io) "Data Input/Output", 39 ~{LB} (in) "Lower-byte Control (I/O0-I/O7)", 40 ~{UB} (in) "Upper-byte Control (I/O8-I/O15)", 41 ~{OE} (in) "Output Enable Input", 42 A2 (in) "Address Input", 43 A1 (in) "Address Input", 44 A0 (in) "Address Input"

## IS61WV3216DBLL-8TLI-TR
designator U?
512 K High Speed Asynchronous CMOS SRAM, 32 K x 16, -40 to 85 degC, 44-Pin SOP (TSOP-2-44), Pb-Free; Manufacturer: Integrated Silicon Solution Inc (ISSI); PartNumber: IS61WV3216DBLL-8TLI-TR; Density: 512K; Organization: 32K x 16; Packing: Tape & Reel; Speed (ns): 8
footprint ISSI-TSOP-2-44_N (SOP, 44-Leads, Body 18.5x10.3mm, Pitch 0.8mm, IPC Medium Density)
pins: 1 NC "No Connection", 2 A14 (in) "Address Input", 3 A13 (in) "Address Input", 4 A12 (in) "Address Input", 5 A11 (in) "Address Input", 6 ~{CE} (in) "Chip Enable Input", 7 I/O0 (io) "Data Input/Output", 8 I/O1 (io) "Data Input/Output", 9 I/O2 (io) "Data Input/Output", 10 I/O3 (io) "Data Input/Output", 11 VDD (power) "Power", 12 GND (power) "Ground", 13 I/O4 (io) "Data Input/Output", 14 I/O5 (io) "Data Input/Output", 15 I/O6 (io) "Data Input/Output", 16 I/O7 (io) "Data Input/Output", 17 ~{WE} (in) "Write Enable Input", 18 A10 (in) "Address Input", 19 A9 (in) "Address Input", 20 A8 (in) "Address Input", 21 A7 (in) "Address Input", 22 NC "No Connection", 23 NC "No Connection", 24 A6 (in) "Address Input", 25 A5 (in) "Address Input", 26 A4 (in) "Address Input", 27 A3 (in) "Address Input", 28 NC "No Connection", 29 I/O8 (io) "Data Input/Output", 30 I/O9 (io) "Data Input/Output", 31 I/O10 (io) "Data Input/Output", 32 I/O11 (io) "Data Input/Output", 33 VDD (power) "Power", 34 GND (power) "Ground", 35 I/O12 (io) "Data Input/Output", 36 I/O13 (io) "Data Input/Output", 37 I/O14 (io) "Data Input/Output", 38 I/O15 (io) "Data Input/Output", 39 ~{LB} (in) "Lower-byte Control (I/O0-I/O7)", 40 ~{UB} (in) "Upper-byte Control (I/O8-I/O15)", 41 ~{OE} (in) "Output Enable Input", 42 A2 (in) "Address Input", 43 A1 (in) "Address Input", 44 A0 (in) "Address Input"

## IS61WV3216DBLL-10BI
designator U?
512 K High Speed Asynchronous CMOS SRAM, 32 K x 16, -40 to 85 degC, 48-Pin BGA (TF-BGA-48); Manufacturer: Integrated Silicon Solution Inc (ISSI); PartNumber: IS61WV3216DBLL-10BI; Density: 512K; Organization: 32K x 16; Packing: Tray / Tube; Speed (ns): 10
footprint ISSI-TF-BGA-48-6000X8000DE (BGA, 48-Balls, Body 8x6mm, Pitch 0.75mm)
part A pins: A1 ~{LB} (in) "Lower-byte Control(I/O0-I/O7)", A2 ~{OE} (in) "Output Enable Input", A3 A0 (in) "Address Input", A4 A1 (in) "Address Input", A5 A2 (in) "Address Input", B1 I/O8 (io) "Data Input/Output", B2 ~{UB} (in) "Upper-byte Control(I/O8-I/O15)", B3 A3 (in) "Address Input", B4 A4 (in) "Address Input", B5 ~{CE} (in) "Chip Enable Input", B6 I/O0 (io) "Data Input/Output", C1 I/O9 (io) "Data Input/Output", C2 I/O10 (io) "Data Input/Output", C3 A5 (in) "Address Input", C4 A6 (in) "Address Input", C5 I/O1 (io) "Data Input/Output", C6 I/O2 (io) "Data Input/Output", D1 GND (power) "Ground", D2 I/O11 (io) "Data Input/Output", D4 A7 (in) "Address Input", D5 I/O3 (io) "Data Input/Output", D6 VDD (power) "Power", E1 VDD (power) "Power", E2 I/O12 (io) "Data Input/Output", E5 I/O4 (io) "Data Input/Output", E6 GND (power) "Ground", F1 I/O14 (io) "Data Input/Output", F2 I/O13 (io) "Data Input/Output", F3 A14 (in) "Address Input", F5 I/O5 (io) "Data Input/Output", F6 I/O6 (io) "Data Input/Output", G1 I/O15 (io) "Data Input/Output", G3 A12 (in) "Address Input", G4 A13 (in) "Address Input", G5 ~{WE} (in) "Write Enable Input", G6 I/O7 (io) "Data Input/Output", H2 A8 (in) "Address Input", H3 A9 (in) "Address Input", H4 A10 (in) "Address Input", H5 A11 (in) "Address Input"
part B pins: A6 NC "No Connection", D3 NC "No Connection", E3 NC "No Connection", E4 NC "No Connection", F4 NC "No Connection", G2 NC "No Connection", H1 NC "No Connection", H6 NC "No Connection"

## IS61WV3216DBLL-10BI-TR
designator U?
512 K High Speed Asynchronous CMOS SRAM, 32 K x 16, -40 to 85 degC, 48-Pin BGA (TF-BGA-48); Manufacturer: Integrated Silicon Solution Inc (ISSI); PartNumber: IS61WV3216DBLL-10BI-TR; Density: 512K; Organization: 32K x 16; Packing: Tape & Reel; Speed (ns): 10
footprint ISSI-TF-BGA-48-6000X8000DE (BGA, 48-Balls, Body 8x6mm, Pitch 0.75mm)
part A pins: A1 ~{LB} (in) "Lower-byte Control(I/O0-I/O7)", A2 ~{OE} (in) "Output Enable Input", A3 A0 (in) "Address Input", A4 A1 (in) "Address Input", A5 A2 (in) "Address Input", B1 I/O8 (io) "Data Input/Output", B2 ~{UB} (in) "Upper-byte Control(I/O8-I/O15)", B3 A3 (in) "Address Input", B4 A4 (in) "Address Input", B5 ~{CE} (in) "Chip Enable Input", B6 I/O0 (io) "Data Input/Output", C1 I/O9 (io) "Data Input/Output", C2 I/O10 (io) "Data Input/Output", C3 A5 (in) "Address Input", C4 A6 (in) "Address Input", C5 I/O1 (io) "Data Input/Output", C6 I/O2 (io) "Data Input/Output", D1 GND (power) "Ground", D2 I/O11 (io) "Data Input/Output", D4 A7 (in) "Address Input", D5 I/O3 (io) "Data Input/Output", D6 VDD (power) "Power", E1 VDD (power) "Power", E2 I/O12 (io) "Data Input/Output", E5 I/O4 (io) "Data Input/Output", E6 GND (power) "Ground", F1 I/O14 (io) "Data Input/Output", F2 I/O13 (io) "Data Input/Output", F3 A14 (in) "Address Input", F5 I/O5 (io) "Data Input/Output", F6 I/O6 (io) "Data Input/Output", G1 I/O15 (io) "Data Input/Output", G3 A12 (in) "Address Input", G4 A13 (in) "Address Input", G5 ~{WE} (in) "Write Enable Input", G6 I/O7 (io) "Data Input/Output", H2 A8 (in) "Address Input", H3 A9 (in) "Address Input", H4 A10 (in) "Address Input", H5 A11 (in) "Address Input"
part B pins: A6 NC "No Connection", D3 NC "No Connection", E3 NC "No Connection", E4 NC "No Connection", F4 NC "No Connection", G2 NC "No Connection", H1 NC "No Connection", H6 NC "No Connection"

## IS61WV3216DBLL-10BLI
designator U?
512 K High Speed Asynchronous CMOS SRAM, 32 K x 16, -40 to 85 degC, 48-Pin BGA (TF-BGA-48), Pb-Free; Manufacturer: Integrated Silicon Solution Inc (ISSI); PartNumber: IS61WV3216DBLL-10BLI; Density: 512K; Organization: 32K x 16; Packing: Tray / Tube; Speed (ns): 10
footprint ISSI-TF-BGA-48-6000X8000DE (BGA, 48-Balls, Body 8x6mm, Pitch 0.75mm)
part A pins: A1 ~{LB} (in) "Lower-byte Control(I/O0-I/O7)", A2 ~{OE} (in) "Output Enable Input", A3 A0 (in) "Address Input", A4 A1 (in) "Address Input", A5 A2 (in) "Address Input", B1 I/O8 (io) "Data Input/Output", B2 ~{UB} (in) "Upper-byte Control(I/O8-I/O15)", B3 A3 (in) "Address Input", B4 A4 (in) "Address Input", B5 ~{CE} (in) "Chip Enable Input", B6 I/O0 (io) "Data Input/Output", C1 I/O9 (io) "Data Input/Output", C2 I/O10 (io) "Data Input/Output", C3 A5 (in) "Address Input", C4 A6 (in) "Address Input", C5 I/O1 (io) "Data Input/Output", C6 I/O2 (io) "Data Input/Output", D1 GND (power) "Ground", D2 I/O11 (io) "Data Input/Output", D4 A7 (in) "Address Input", D5 I/O3 (io) "Data Input/Output", D6 VDD (power) "Power", E1 VDD (power) "Power", E2 I/O12 (io) "Data Input/Output", E5 I/O4 (io) "Data Input/Output", E6 GND (power) "Ground", F1 I/O14 (io) "Data Input/Output", F2 I/O13 (io) "Data Input/Output", F3 A14 (in) "Address Input", F5 I/O5 (io) "Data Input/Output", F6 I/O6 (io) "Data Input/Output", G1 I/O15 (io) "Data Input/Output", G3 A12 (in) "Address Input", G4 A13 (in) "Address Input", G5 ~{WE} (in) "Write Enable Input", G6 I/O7 (io) "Data Input/Output", H2 A8 (in) "Address Input", H3 A9 (in) "Address Input", H4 A10 (in) "Address Input", H5 A11 (in) "Address Input"
part B pins: A6 NC "No Connection", D3 NC "No Connection", E3 NC "No Connection", E4 NC "No Connection", F4 NC "No Connection", G2 NC "No Connection", H1 NC "No Connection", H6 NC "No Connection"

## IS61WV3216DBLL-10BLI-TR
designator U?
512 K High Speed Asynchronous CMOS SRAM, 32 K x 16, -40 to 85 degC, 48-Pin BGA (TF-BGA-48), Pb-Free; Manufacturer: Integrated Silicon Solution Inc (ISSI); PartNumber: IS61WV3216DBLL-10BLI-TR; Density: 512K; Organization: 32K x 16; Packing: Tape & Reel; Speed (ns): 10
footprint ISSI-TF-BGA-48-6000X8000DE (BGA, 48-Balls, Body 8x6mm, Pitch 0.75mm)
part A pins: A1 ~{LB} (in) "Lower-byte Control(I/O0-I/O7)", A2 ~{OE} (in) "Output Enable Input", A3 A0 (in) "Address Input", A4 A1 (in) "Address Input", A5 A2 (in) "Address Input", B1 I/O8 (io) "Data Input/Output", B2 ~{UB} (in) "Upper-byte Control(I/O8-I/O15)", B3 A3 (in) "Address Input", B4 A4 (in) "Address Input", B5 ~{CE} (in) "Chip Enable Input", B6 I/O0 (io) "Data Input/Output", C1 I/O9 (io) "Data Input/Output", C2 I/O10 (io) "Data Input/Output", C3 A5 (in) "Address Input", C4 A6 (in) "Address Input", C5 I/O1 (io) "Data Input/Output", C6 I/O2 (io) "Data Input/Output", D1 GND (power) "Ground", D2 I/O11 (io) "Data Input/Output", D4 A7 (in) "Address Input", D5 I/O3 (io) "Data Input/Output", D6 VDD (power) "Power", E1 VDD (power) "Power", E2 I/O12 (io) "Data Input/Output", E5 I/O4 (io) "Data Input/Output", E6 GND (power) "Ground", F1 I/O14 (io) "Data Input/Output", F2 I/O13 (io) "Data Input/Output", F3 A14 (in) "Address Input", F5 I/O5 (io) "Data Input/Output", F6 I/O6 (io) "Data Input/Output", G1 I/O15 (io) "Data Input/Output", G3 A12 (in) "Address Input", G4 A13 (in) "Address Input", G5 ~{WE} (in) "Write Enable Input", G6 I/O7 (io) "Data Input/Output", H2 A8 (in) "Address Input", H3 A9 (in) "Address Input", H4 A10 (in) "Address Input", H5 A11 (in) "Address Input"
part B pins: A6 NC "No Connection", D3 NC "No Connection", E3 NC "No Connection", E4 NC "No Connection", F4 NC "No Connection", G2 NC "No Connection", H1 NC "No Connection", H6 NC "No Connection"

## IS61WV3216DBLL-10TI
designator U?
512 K High Speed Asynchronous CMOS SRAM, 32 K x 16, -40 to 85 degC, 44-Pin SOP (TSOP-2-44); Manufacturer: Integrated Silicon Solution Inc (ISSI); PartNumber: IS61WV3216DBLL-10TI; Density: 512K; Organization: 32K x 16; Packing: Tray / Tube; Speed (ns): 10
footprint ISSI-TSOP-2-44_N (SOP, 44-Leads, Body 18.5x10.3mm, Pitch 0.8mm, IPC Medium Density)
pins: 1 NC "No Connection", 2 A14 (in) "Address Input", 3 A13 (in) "Address Input", 4 A12 (in) "Address Input", 5 A11 (in) "Address Input", 6 ~{CE} (in) "Chip Enable Input", 7 I/O0 (io) "Data Input/Output", 8 I/O1 (io) "Data Input/Output", 9 I/O2 (io) "Data Input/Output", 10 I/O3 (io) "Data Input/Output", 11 VDD (power) "Power", 12 GND (power) "Ground", 13 I/O4 (io) "Data Input/Output", 14 I/O5 (io) "Data Input/Output", 15 I/O6 (io) "Data Input/Output", 16 I/O7 (io) "Data Input/Output", 17 ~{WE} (in) "Write Enable Input", 18 A10 (in) "Address Input", 19 A9 (in) "Address Input", 20 A8 (in) "Address Input", 21 A7 (in) "Address Input", 22 NC "No Connection", 23 NC "No Connection", 24 A6 (in) "Address Input", 25 A5 (in) "Address Input", 26 A4 (in) "Address Input", 27 A3 (in) "Address Input", 28 NC "No Connection", 29 I/O8 (io) "Data Input/Output", 30 I/O9 (io) "Data Input/Output", 31 I/O10 (io) "Data Input/Output", 32 I/O11 (io) "Data Input/Output", 33 VDD (power) "Power", 34 GND (power) "Ground", 35 I/O12 (io) "Data Input/Output", 36 I/O13 (io) "Data Input/Output", 37 I/O14 (io) "Data Input/Output", 38 I/O15 (io) "Data Input/Output", 39 ~{LB} (in) "Lower-byte Control (I/O0-I/O7)", 40 ~{UB} (in) "Upper-byte Control (I/O8-I/O15)", 41 ~{OE} (in) "Output Enable Input", 42 A2 (in) "Address Input", 43 A1 (in) "Address Input", 44 A0 (in) "Address Input"

## IS61WV3216DBLL-10TI-TR
designator U?
512 K High Speed Asynchronous CMOS SRAM, 32 K x 16, -40 to 85 degC, 44-Pin SOP (TSOP-2-44); Manufacturer: Integrated Silicon Solution Inc (ISSI); PartNumber: IS61WV3216DBLL-10TI-TR; Density: 512K; Organization: 32K x 16; Packing: Tape & Reel; Speed (ns): 10
footprint ISSI-TSOP-2-44_N (SOP, 44-Leads, Body 18.5x10.3mm, Pitch 0.8mm, IPC Medium Density)
pins: 1 NC "No Connection", 2 A14 (in) "Address Input", 3 A13 (in) "Address Input", 4 A12 (in) "Address Input", 5 A11 (in) "Address Input", 6 ~{CE} (in) "Chip Enable Input", 7 I/O0 (io) "Data Input/Output", 8 I/O1 (io) "Data Input/Output", 9 I/O2 (io) "Data Input/Output", 10 I/O3 (io) "Data Input/Output", 11 VDD (power) "Power", 12 GND (power) "Ground", 13 I/O4 (io) "Data Input/Output", 14 I/O5 (io) "Data Input/Output", 15 I/O6 (io) "Data Input/Output", 16 I/O7 (io) "Data Input/Output", 17 ~{WE} (in) "Write Enable Input", 18 A10 (in) "Address Input", 19 A9 (in) "Address Input", 20 A8 (in) "Address Input", 21 A7 (in) "Address Input", 22 NC "No Connection", 23 NC "No Connection", 24 A6 (in) "Address Input", 25 A5 (in) "Address Input", 26 A4 (in) "Address Input", 27 A3 (in) "Address Input", 28 NC "No Connection", 29 I/O8 (io) "Data Input/Output", 30 I/O9 (io) "Data Input/Output", 31 I/O10 (io) "Data Input/Output", 32 I/O11 (io) "Data Input/Output", 33 VDD (power) "Power", 34 GND (power) "Ground", 35 I/O12 (io) "Data Input/Output", 36 I/O13 (io) "Data Input/Output", 37 I/O14 (io) "Data Input/Output", 38 I/O15 (io) "Data Input/Output", 39 ~{LB} (in) "Lower-byte Control (I/O0-I/O7)", 40 ~{UB} (in) "Upper-byte Control (I/O8-I/O15)", 41 ~{OE} (in) "Output Enable Input", 42 A2 (in) "Address Input", 43 A1 (in) "Address Input", 44 A0 (in) "Address Input"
